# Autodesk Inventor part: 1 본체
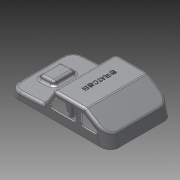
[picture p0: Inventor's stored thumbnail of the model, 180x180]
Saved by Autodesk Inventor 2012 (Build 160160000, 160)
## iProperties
Created: 2015-05
Part Number: 1 본체
Material: Default
Document SubType Name: Modeling
Designer: Owner
Density: 1 g/cm^3
Author: Owner
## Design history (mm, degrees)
sketch "스케치1"
  geometry: L1 (0, 0)-(122, 0); L2 (2.174, 9.114)-(42, 11.201); L3 (42, 11.201)-(54.372, 31); L4 (0, 0)-(0, 9); L5 (2.174, 9.114)-(0, 9); L6 (54.372, 31)-(92, 31); L7 (92, 31)-(118.378, 14.517); L8 (0, 0)-(0, 1); L9 (2.174, 9.114)-(0, 1); L10 (118.378, 14.517)-(122, 1); L11 (122, 1)-(122, 0)
  constraints: 22 end point, 3 point on line, 2 perpendicular, 1 collinear, 1 horizontal, 1 parallel
  dimensions: "d0" = 122 distance of L1.start L1.end; "d6" = 125 deg angle of L3 L2; "d8" = 42 horizontal distance of L2.end L1.start; "d10" = 3 deg angle of L1 L2; "d15" = 9 distance of L1.start L4.end; "d24" = 31 distance between parallel lines of L1 L6; "d26" = 30 horizontal distance of L1.end L6.end; "d52" = 1 distance of L1.start L8.end; "d53" = 105 deg angle of L1 L9; "d54" = 1 distance of L10.end L1.end; "d56" = 105 deg angle of L1 L10
extrude "돌출1" new body sketch "스케치1" stored distance "d12" = 76; taper "d13" = 0 deg
fillet "모깎기1" dims "d14" = 12
sketch "스케치3"
  geometry: L1 (92, 31)-(118.378, 14.517) reference; L2 (54.372, 31)-(92, 31) reference; L3 (42, 11.201)-(54.372, 31) reference; L4 (122, 0)-(0, 0) reference; L5 (47.77, 11)-(57.143, 26); L6 (90.566, 26)-(114.571, 11); L7 (81.77, 26)-(81.77, 11); L8 (86.571, 11)-(86.571, 26); L9 (57.143, 26)-(81.77, 26); L10 (86.571, 26)-(90.566, 26); L11 (114.571, 11)-(86.571, 11); L12 (81.77, 11)-(47.77, 11); 3 further points
  constraints: 16 end point, 9 parallel, 2 collinear, 2 perpendicular
  dimensions: "d28" = 34 distance of L7.end L5.start; "d29" = 28 distance of L6.end L8.start; "d30" = 5 distance between parallel lines of L5 L3; "d32" = 5 distance between parallel lines of L1 L6; "d33" = 5 distance between parallel lines of L9 L2; "d34" = 15 distance between parallel lines of L12 L9
sketch "스케치4"
  geometry: L1 (11, 9.576)-(12.556, 14.665); L2 (12.556, 14.665)-(28.921, 15.523); L3 (28.921, 15.523)-(31, 10.625); L4 (42, 11.201)-(14.774, 9.774) reference; L5 (2.174, 9.114)-(14.774, 9.774) reference; 1 further point
  constraints: 6 end point, 2 point on line
  dimensions: "d41" = 20 horizontal distance of L3.end L1.start; "d42" = 11 horizontal distance of L1.start point (0, 0); "d58" = 70 deg angle of L5 L1; "d59" = 70 deg angle of L4 L3; "d60" = 5 distance between parallel lines of L4 L2
extrude "돌출3" join sketch "스케치4" stored distance "d43" = 26; taper "d44" = 0 deg
fillet "모깎기5" dims "d145" = 3
fillet "모깎기4" dims "d49" = 3
feature "쉘3" dims "d45" = 2
extrude "돌출4" cut sketch "스케치3" stored distance "d46" = 26; taper "d47" = 0 deg
fillet "모깎기3" dims "d48" = 3
sketch "스케치6"
  geometry: L1 (109.845, -66.479)-(109.845, -9.521) reference; L2 (97.689, 0)-(0, 0) reference; L3 (-12.155, -9.521)-(-12.155, -66.479) reference; L4 (0, -76)-(97.689, -76) reference; L5 (0, -1)-(97.689, -1); L6 (108.845, -9.632)-(108.845, -66.368); L7 (97.689, -75)-(0, -75); L8 (-11.155, -66.368)-(-11.155, -9.632); 5 further points; 4 other entities
  constraints: 8 end point, 7 parallel, 16 other
  dimensions: "d67" = 1 distance between parallel lines of L5 L2
extrude "돌출6" cut sketch "스케치6" distance "d68" = 1; taper "d69" = 0 deg
sketch "스케치7"
  geometry: L1 (-12.155, -64)-(-12.155, -12) reference; L2 (0.268, 0)-(97.421, 0) reference; L3 (0, -75)-(97.689, -75) reference; L4 (48.845, 0)-(48.845, -75); C1 r 3 at (8.845, -38); C2 r 3 at (88.845, -38); C3 r 3 at (48.845, -60); C4 r 3 at (48.845, -16); 2 further points
  constraints: 4 centre point, 3 equal radius, 3 midpoint, 2 end point, 2 horizontal alignment, 2 point on line
  dimensions: "d72" = 6 diameter of C1; "d73" = 40 distance from line of L4 C1.centre; "d74" = 40 distance from line of L4 C2.centre; "d75" = 22 vertical distance of point (-12.155, -38) C3.centre; "d76" = 22 vertical distance of point (-12.155, -38) C4.centre
extrude "돌출7" join sketch "스케치7" stored distance "d77" = 1; taper "d78" = 0 deg
sketch "스케치12"
  geometry: L1 (26.564, 13.396)-(15.122, 12.797) reference; L2 (18, 1)-(18, 12.947) reference; L3 (24, 1)-(24, 13.262) reference; L4 (16, 3)-(26, 3); L5 (26, 3)-(27.78, 13.093); L6 (16, 3)-(14.28, 12.753); L7 (14.059, 12.741)-(15.122, 12.797) reference; L8 (26.564, 13.396)-(27.627, 13.452) reference; L9 (27.627, 13.452)-(28.338, 11.777) reference; L10 (109.845, 0)-(12.155, 0) reference; 1 further point
  constraints: 6 end point, 2 point on line, 1 perpendicular
  dimensions: "d148" = 10 distance of L4.start L4.end; "d149" = 2 distance from line of L2 L4.start; "d150" = 10 deg angle of L2 L6; "d151" = 10 deg angle of L3 L5; "d152" = 3 distance between parallel lines of L10 L4
extrude "돌출9" join sketch "스케치12" stored distance "d153" = 2; taper "d154" = 0 deg
sketch "스케치13"
  geometry: L1 (104.215, 21.009)-(91.427, 29) reference; L2 (104.215, 21.009)-(116.65, 13.239) reference; L3 (91.415, 29)-(96, 3); L4 (96, 3)-(106, 3); L5 (106, 3)-(108.683, 18.217); L6 (109.845, 0)-(12.155, 0) reference; L7 (104, 1)-(104, 21.143) reference; L8 (91.427, 29)-(55.48, 29) reference; 1 further point
  constraints: 6 end point, 2 point on line, 1 horizontal
  dimensions: "d155" = 3 distance between parallel lines of L6 L4; "d156" = 10 distance of L3.end L4.end; "d157" = 2 distance from line of L4.end L7; "d158" = 10 deg angle of L7 L3; "d159" = 10 deg angle of L5 L7
extrude "돌출10" join sketch "스케치13" stored distance "d160" = 2; taper "d161" = 0 deg
node "작업 평면3"
sketch "스케치14"
  geometry: L1 (58, 1)-(58, 29) reference; L2 (64, 1)-(64, 29) reference; L3 (91.427, 29)-(55.48, 29) reference; L4 (55.48, 29)-(43.144, 9.258) reference; L5 (52.31, 23.927)-(56, 3); L6 (56, 3)-(66, 3); L7 (66, 3)-(70.585, 29); L8 (109.845, 0)-(12.155, 0) reference; 1 further point
  constraints: 6 end point, 2 point on line, 1 parallel
  dimensions: "d163" = 10 deg angle of L1 L5; "d164" = 10 deg angle of L7 L2; "d165" = 3 distance between parallel lines of L8 L6; "d166" = 10 distance of L5.end L6.end; "d167" = 2 distance from line of L1 L5.end
extrude "돌출11" join sketch "스케치14" stored distance "d168" = 2; taper "d169" = 0 deg
hole "구멍1" diameter "d97" = 3.242; stored, may be unused: countersink angle "d101" = 90 deg, drill point angle "d103" = 118 deg; dims "d95" = 10, "d96" = 10, "d98" = 9, "d99" = 4, "d100" = 2, "d102" = 11
hole "구멍2" diameter "d106" = 3.242; stored, may be unused: countersink angle "d110" = 90 deg, drill point angle "d112" = 118 deg; dims "d104" = 10, "d105" = 10, "d107" = 9, "d108" = 4, "d109" = 2, "d111" = 11
hole "구멍3" diameter "d115" = 3.242; stored, may be unused: countersink angle "d119" = 90 deg, drill point angle "d121" = 118 deg; dims "d113" = 10, "d114" = 10, "d116" = 9, "d117" = 4, "d118" = 2, "d120" = 11
hole "구멍4" diameter "d124" = 3.242; stored, may be unused: countersink angle "d128" = 90 deg, drill point angle "d130" = 118 deg; dims "d122" = 10, "d123" = 10, "d125" = 9, "d126" = 4, "d127" = 2, "d129" = 11
node "작업 평면1"
sketch "스케치10"
  geometry: L1 (-1, -26)-(-1, -38) reference; L2 (-1, -26)-(-1, 26) reference; A1 r 4 centre (-1, -10) between (-1, -6) and (-1, -14); A2 r 4 centre (-1, -21) between (-1, -17) and (-1, -25); 1 further point
  constraints: 6 point on line, 4 point on circle, 2 centre point
  dimensions: "d132" = 10 vertical distance of point (0, 0) A1.centre; "d133" = 11 distance of A1.centre A2.centre; "d134" = 4 radius of A2; "d135" = 4 radius of A1
extrude "돌출8" join sketch "스케치10" stored distance "d136" = 2; taper "d137" = 0 deg
node "작업 평면2"
sketch "스케치11"
  geometry: L1 (66.628, 66.368)-(66.628, 9.632) reference; 2 further points
  constraints: 1 horizontal alignment, 1 other
  dimensions: "d139" = 50 distance from line of point (16.628, 38) L1
feature "엠보싱1" sketch "스케치11" dims "d140" = 0.5, "d141" = 0
chamfer "모따기1" distance "d142" = 1; stored, may be unused: second distance "d143" = 2, angle "d144" = 45 deg
fillet "모깎기6" dims "d146" = 3
fillet "모깎기7" dims "d147" = 3
node "솔리드1"
mirror "대칭2"
mirror "대칭1"
other parameters: "d131" = -2, "d162" = 22
